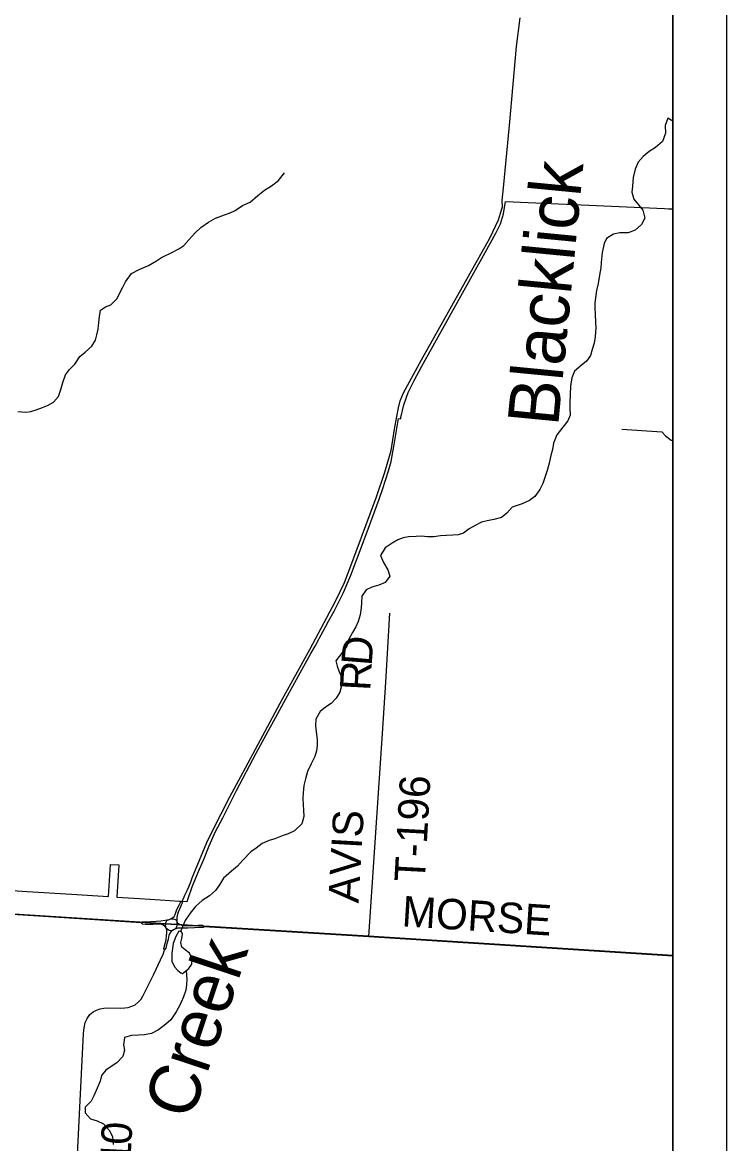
# Model space of a CAD drawing. Extents: x 208586767.6 to 208586821.4, y -134301046.9 to -134301022.9.
# Drawn here: x 208586783.617 to 208586784.928, y -134301027.656 to -134301025.568 of the extents above; entities that cross this region are included whole.
import ezdxf

# ---------------------------------------------------------------- set-up
doc = ezdxf.new("R2010")
doc.units = 0
for name, color, linetype in [('GM_X_Corporation', 7, 'Continuous'), ('GM_X_County_Road', 7, 'Continuous'), ('GM_X_County_Road_Text', 7, 'Continuous'), ('GM_X_Minor_Lake', 7, 'Continuous'), ('GM_X_Minor_River', 7, 'Continuous'), ('GM_X_Minor_River_Text', 7, 'Continuous'), ('GM_X_Township_Road', 7, 'Continuous'), ('GM_X_Township_Road_Text', 7, 'Continuous'), ('SH_Data', 7, 'Continuous')]:
    doc.layers.add(name, color=color, linetype=linetype)

msp = doc.modelspace()

# ---------------------------------------------------------------- linework, layer by layer
at = {"layer": 'GM_X_Corporation'}
for points in [[(208586781.2713, -134301027.0897), (208586781.6677, -134301027.1118), (208586781.7056, -134301027.1139), (208586781.7344, -134301027.1148), (208586781.8329, -134301027.1207), (208586781.8549, -134301027.122), (208586781.8736, -134301027.1231), (208586781.98, -134301027.1295), (208586782.1685, -134301027.1422), (208586782.6086, -134301027.1669), (208586782.6378, -134301027.1684), (208586782.648, -134301027.1691), (208586782.72, -134301027.1729), (208586782.8221, -134301027.178), (208586783.5221, -134301027.2233), (208586783.9036, -134301027.2474), (208586784.2616, -134301027.2694), (208586784.8283, -134301027.3051), (208586784.8283, -134301024.0407), (208586780.8686, -134301024.0407)], [(208586783.5332, -134301027.18), (208586783.6258, -134301027.1859), (208586783.7083, -134301027.1912), (208586783.7768, -134301027.1955), (208586783.7805, -134301027.1358), (208586783.7965, -134301027.1367), (208586783.7926, -134301027.1965), (208586783.8345, -134301027.1992), (208586783.873, -134301027.2016), (208586783.9093, -134301027.2039), (208586783.9118, -134301027.2041), (208586783.9236, -134301027.2048), (208586783.926, -134301027.1976), (208586783.933, -134301027.1775), (208586783.9397, -134301027.1609), (208586783.9466, -134301027.1445), (208586783.9538, -134301027.1281), (208586783.9645, -134301027.1012), (208586783.9765, -134301027.0747), (208586783.9898, -134301027.0489), (208586784.0157, -134301026.9984), (208586784.0524, -134301026.9285), (208586784.1076, -134301026.8271), (208586784.1537, -134301026.743), (208586784.1617, -134301026.7291), (208586784.1695, -134301026.7152), (208586784.1771, -134301026.7012), (208586784.1871, -134301026.6826), (208586784.1971, -134301026.6639), (208586784.207, -134301026.6453), (208586784.2146, -134301026.6294), (208586784.2217, -134301026.6133), (208586784.2285, -134301026.597), (208586784.2514, -134301026.5363), (208586784.2547, -134301026.5274), (208586784.257, -134301026.5212), (208586784.2814, -134301026.4555), (208586784.2876, -134301026.4378), (208586784.2931, -134301026.4204), (208586784.2983, -134301026.4029), (208586784.3038, -134301026.3854), (208586784.3094, -134301026.3536), (208586784.3174, -134301026.3054), (208586784.3214, -134301026.3056), (208586784.3217, -134301026.3036), (208586784.327, -134301026.2798), (208586784.3351, -134301026.2569), (208586784.3462, -134301026.2344), (208586784.3605, -134301026.208), (208586784.4786, -134301025.9959), (208586784.4987, -134301025.96), (208586784.5071, -134301025.9425), (208586784.5129, -134301025.9239), (208586784.5158, -134301025.9048), (208586784.5162, -134301025.9009), (208586784.8128, -134301025.9142), (208586784.82, -134301025.9145), (208586784.8283, -134301025.9149), (208586784.8283, -134301024.3829)], [(208586780.4561, -134301030.8407), (208586784.8283, -134301030.8407), (208586784.8283, -134301027.3051), (208586784.2616, -134301027.2694), (208586783.9036, -134301027.2474), (208586783.5221, -134301027.2233), (208586782.8221, -134301027.178), (208586782.72, -134301027.1729), (208586782.648, -134301027.1691), (208586782.6378, -134301027.1684), (208586782.6086, -134301027.1669), (208586782.1685, -134301027.1422), (208586781.98, -134301027.1295), (208586781.8736, -134301027.1231), (208586781.8549, -134301027.122), (208586781.8329, -134301027.1207), (208586781.7344, -134301027.1148), (208586781.7056, -134301027.1139), (208586781.6677, -134301027.1118), (208586781.2713, -134301027.0897)]]:
    msp.add_lwpolyline(points, dxfattribs=at)
at = {"layer": 'GM_X_County_Road'}
msp.add_line((208586783.5223, -134301027.2238), (208586783.837, -134301027.2437), dxfattribs=at)
for points in [[(208586783.9304, -134301027.168), (208586783.933, -134301027.1609), (208586783.9603, -134301027.0951), (208586783.9705, -134301027.0734), (208586784.0033, -134301027.0099), (208586784.0278, -134301026.964), (208586784.101, -134301026.8274), (208586784.1518, -134301026.7352), (208586784.2001, -134301026.6453), (208586784.2166, -134301026.6107), (208586784.2303, -134301026.5749), (208586784.2644, -134301026.4827), (208586784.2764, -134301026.4511), (208586784.2917, -134301026.4055), (208586784.2962, -134301026.3904), (208586784.3035, -134301026.365), (208586784.3095, -134301026.3251), (208586784.314, -134301026.3018), (208586784.317, -134301026.2853), (208586784.3202, -134301026.2723), (208586784.3268, -134301026.2575), (208586784.3598, -134301026.1959), (208586784.4475, -134301026.0399), (208586784.4872, -134301025.9696), (208586784.5034, -134301025.9351), (208586784.5071, -134301025.9231), (208586784.5109, -134301025.9111), (208586784.5102, -134301025.8995), (208586784.513, -134301025.8759), (208586784.5238, -134301025.7598), (208586784.531, -134301025.6828), (208586784.5371, -134301025.6123), (208586784.5436, -134301025.5592)], [(208586783.9147, -134301027.2034), (208586783.9195, -134301027.1928), (208586783.9241, -134301027.1832), (208586783.9267, -134301027.1772), (208586783.9304, -134301027.168)], [(208586783.8898, -134301027.2382), (208586783.8953, -134301027.2361), (208586783.8992, -134301027.233), (208586783.9012, -134301027.2289), (208586783.9046, -134301027.22), (208586783.909, -134301027.2103), (208586783.9115, -134301027.2053), (208586783.9147, -134301027.2034)], [(208586783.905, -134301027.2441), (208586783.9048, -134301027.2397), (208586783.905, -134301027.2342), (208586783.9062, -134301027.2284), (208586783.9074, -134301027.2238), (208586783.9099, -134301027.2183), (208586783.9132, -134301027.2111), (208586783.9149, -134301027.207), (208586783.9147, -134301027.2034)], [(208586783.837, -134301027.2437), (208586783.8398, -134301027.2429), (208586783.8477, -134301027.2425), (208586783.8558, -134301027.2422), (208586783.8658, -134301027.2416), (208586783.8746, -134301027.2406), (208586783.8829, -134301027.2394), (208586783.8898, -134301027.2382), (208586783.8916, -134301027.2376), (208586783.895, -134301027.2371), (208586783.8977, -134301027.2373), (208586783.9, -134301027.238), (208586783.9022, -134301027.2389), (208586783.9042, -134301027.2412), (208586783.905, -134301027.2441), (208586783.9078, -134301027.2465), (208586783.9136, -134301027.2492), (208586783.917, -134301027.2497), (208586783.9227, -134301027.2496), (208586783.9345, -134301027.2494), (208586783.9443, -134301027.2492), (208586783.9524, -134301027.2492), (208586783.9553, -134301027.2511)], [(208586783.837, -134301027.2437), (208586783.8398, -134301027.2464), (208586783.8459, -134301027.247), (208586783.8535, -134301027.2472), (208586783.8595, -134301027.2468), (208586783.8671, -134301027.2465), (208586783.8724, -134301027.2465), (208586783.8759, -134301027.2469), (208586783.8789, -134301027.2484), (208586783.8818, -134301027.251), (208586783.8841, -134301027.2536)], [(208586783.8841, -134301027.2536), (208586783.8836, -134301027.251), (208586783.883, -134301027.2485), (208586783.8833, -134301027.2455), (208586783.8842, -134301027.2429), (208586783.886, -134301027.2404), (208586783.8898, -134301027.2382)], [(208586783.9045, -134301027.2516), (208586783.9051, -134301027.2491), (208586783.905, -134301027.2441)], [(208586783.8812, -134301027.2956), (208586783.8801, -134301027.2923), (208586783.8826, -134301027.2833), (208586783.8843, -134301027.2763), (208586783.8853, -134301027.269), (208586783.8857, -134301027.2631), (208586783.8856, -134301027.2574), (208586783.8841, -134301027.2536)], [(208586783.8812, -134301027.2956), (208586783.8842, -134301027.292), (208586783.8866, -134301027.2832), (208586783.8888, -134301027.2747), (208586783.8898, -134301027.2677), (208586783.8911, -134301027.2643), (208586783.8941, -134301027.2605), (208586783.8964, -134301027.2585), (208586783.8996, -134301027.2566)], [(208586783.8841, -134301027.2536), (208586783.8864, -134301027.256), (208586783.8898, -134301027.258), (208586783.8935, -134301027.2587), (208586783.8963, -134301027.2582), (208586783.8996, -134301027.2566)], [(208586783.8996, -134301027.2566), (208586783.9029, -134301027.2552), (208586783.9074, -134301027.254), (208586783.9134, -134301027.2538), (208586783.9249, -134301027.2536), (208586783.9374, -134301027.2533), (208586783.9531, -134301027.2529), (208586783.9553, -134301027.2511)], [(208586783.8996, -134301027.2566), (208586783.9022, -134301027.2548), (208586783.9042, -134301027.2524), (208586783.9045, -134301027.2516)], [(208586783.9553, -134301027.2511), (208586784.2619, -134301027.27), (208586784.8283, -134301027.3057)], [(208586783.8742, -134301027.3132), (208586783.8787, -134301027.3027), (208586783.8805, -134301027.2971), (208586783.8812, -134301027.2956)], [(208586783.7156, -134301027.7514), (208586783.7306, -134301027.4507), (208586783.7315, -134301027.4398), (208586783.7337, -134301027.4303), (208586783.7372, -134301027.4225), (208586783.7421, -134301027.4155), (208586783.7485, -134301027.4101), (208586783.7547, -134301027.4069), (208586783.7617, -134301027.4045), (208586783.7683, -134301027.4032), (208586783.777, -134301027.4031), (208586783.8001, -134301027.4032), (208586783.8074, -134301027.4031), (208586783.8136, -134301027.402), (208586783.8204, -134301027.4), (208586783.8266, -134301027.3972), (208586783.8325, -134301027.3924), (208586783.8377, -134301027.3868), (208586783.8409, -134301027.3814), (208586783.8444, -134301027.375), (208586783.8613, -134301027.3402), (208586783.8742, -134301027.3132)]]:
    msp.add_lwpolyline(points, dxfattribs=at)
at = {"layer": 'GM_X_Minor_Lake'}
for points in [[(208586784.7331, -134301026.3252), (208586784.8078, -134301026.3302)], [(208586784.8078, -134301026.3302), (208586784.8146, -134301026.3375), (208586784.8252, -134301026.3459), (208586784.8283, -134301026.3467)], [(208586783.9264, -134301027.3293), (208586783.9321, -134301027.3217), (208586783.9326, -134301027.3115), (208586783.9281, -134301027.3008), (208586783.9201, -134301027.2951), (208586783.9137, -134301027.2897), (208586783.9119, -134301027.2814), (208586783.9134, -134301027.2738), (208586783.9146, -134301027.2654), (208586783.9131, -134301027.2613), (208586783.9078, -134301027.2601), (208586783.9025, -134301027.2699), (208586783.8978, -134301027.2828), (208586783.895, -134301027.301), (208586783.8953, -134301027.3158), (208586783.8998, -134301027.3265), (208586783.9062, -134301027.3333), (208586783.9119, -134301027.3379)], [(208586783.9119, -134301027.3379), (208586783.9142, -134301027.3389), (208586783.9148, -134301027.3389), (208586783.9264, -134301027.3293)]]:
    msp.add_lwpolyline(points, dxfattribs=at)
at = {"layer": 'GM_X_Minor_River'}
for points in [[(208586784.8283, -134301025.7514), (208586784.8187, -134301025.7462), (208586784.814, -134301025.7598), (208586784.8147, -134301025.7738), (208586784.8089, -134301025.7894), (208586784.7956, -134301025.8003), (208586784.7841, -134301025.8082), (208586784.7727, -134301025.8176), (208586784.7635, -134301025.8278), (208586784.7577, -134301025.8407), (208586784.7542, -134301025.8562), (208586784.753, -134301025.8725), (208586784.7518, -134301025.8835), (208586784.7555, -134301025.8965), (208586784.7642, -134301025.9071), (208586784.7725, -134301025.9174), (208586784.7758, -134301025.9323), (208586784.7696, -134301025.944), (208586784.7582, -134301025.9545), (208586784.7449, -134301025.9594), (208586784.7297, -134301025.9597), (208586784.7179, -134301025.9619), (208586784.7046, -134301025.9698), (208586784.7003, -134301025.9796), (208586784.6964, -134301025.9963), (208586784.6944, -134301026.0145), (208586784.694, -134301026.0244), (208586784.6916, -134301026.0384), (208586784.6892, -134301026.0536), (208586784.6861, -134301026.0668), (208586784.6845, -134301026.0763), (208586784.6829, -134301026.09), (208586784.6829, -134301026.0998), (208586784.6832, -134301026.1101), (208586784.6839, -134301026.1272), (208586784.6845, -134301026.1367), (208586784.6837, -134301026.1526), (208586784.6817, -134301026.1647), (208586784.6782, -134301026.1769), (208586784.6747, -134301026.1882), (208586784.6671, -134301026.1984), (208586784.6575, -134301026.2067), (208586784.645, -134301026.2169), (208586784.6399, -134301026.2294), (208586784.6376, -134301026.2453), (208586784.6367, -134301026.2605), (208586784.6362, -134301026.2761), (208586784.6366, -134301026.2859), (208586784.6369, -134301026.2988), (208586784.6326, -134301026.3098), (208586784.6234, -134301026.3215), (208586784.6123, -134301026.3359), (208586784.6062, -134301026.351), (208586784.6038, -134301026.3632), (208586784.6011, -134301026.3742), (208586784.598, -134301026.3882), (208586784.5941, -134301026.4022), (208586784.5898, -134301026.4151), (208586784.5863, -134301026.4265), (208586784.5806, -134301026.4378), (208586784.5714, -134301026.4507), (208586784.5611, -134301026.4582), (208586784.5478, -134301026.4642), (208586784.5383, -134301026.4675), (208586784.5288, -134301026.4705), (208586784.5188, -134301026.4815), (208586784.5089, -134301026.4898), (208586784.4945, -134301026.4935), (208586784.4823, -134301026.4957), (208586784.472, -134301026.4986), (208586784.4598, -134301026.5043), (208586784.4488, -134301026.5107), (208586784.4385, -134301026.5189), (208586784.4286, -134301026.5219), (208586784.4184, -134301026.5226), (208586784.4066, -134301026.5233), (208586784.3956, -134301026.524), (208586784.383, -134301026.5254), (208586784.3713, -134301026.5254), (208586784.3599, -134301026.5245), (208586784.35, -134301026.5249), (208586784.3356, -134301026.5255), (208586784.3257, -134301026.5278), (208586784.3158, -134301026.5311), (208586784.3056, -134301026.5375), (208586784.2926, -134301026.5462), (208586784.2838, -134301026.5602), (208586784.2894, -134301026.5735), (208586784.2973, -134301026.5872), (208586784.301, -134301026.599), (208586784.2926, -134301026.6107), (208586784.2808, -134301026.6156), (208586784.2678, -134301026.6193), (208586784.2572, -134301026.6245), (208586784.2488, -134301026.6359)], [(208586783.6084, -134301026.2923), (208586783.6232, -134301026.2932), (208586783.6327, -134301026.2921), (208586783.6426, -134301026.2891), (208586783.654, -134301026.285), (208586783.6635, -134301026.2813), (208586783.6745, -134301026.2749), (208586783.6837, -134301026.2643), (208586783.6883, -134301026.2514), (208586783.6922, -134301026.2382), (208586783.6969, -134301026.2242), (208586783.7045, -134301026.2143), (208586783.7144, -134301026.2041), (208586783.7236, -134301026.1898), (208586783.7336, -134301026.1815), (208586783.7458, -134301026.1705), (208586783.7527, -134301026.1592), (208586783.7554, -134301026.1497), (208586783.7577, -134301026.1387), (208586783.7593, -134301026.1262), (208586783.7602, -134301026.1156), (208586783.7621, -134301026.1038), (208586783.7717, -134301026.0974), (208586783.7812, -134301026.0937), (208586783.7934, -134301026.082), (208586783.7984, -134301026.071), (208586783.8038, -134301026.0608), (208586783.8088, -134301026.051), (208586783.8199, -134301026.0355), (208586783.8343, -134301026.0276), (208586783.8518, -134301026.0201), (208586783.8663, -134301026.0119), (208586783.8759, -134301026.0055), (208586783.896, -134301025.9957), (208586783.9078, -134301025.9893), (208586783.9174, -134301025.9829), (208586783.9269, -134301025.9727), (208586783.9376, -134301025.9603), (208586783.9491, -134301025.9497), (208586783.9636, -134301025.9399), (208586783.9761, -134301025.9321), (208586783.9932, -134301025.9261), (208586784.0035, -134301025.922), (208586784.013, -134301025.9178), (208586784.0264, -134301025.9084), (208586784.0408, -134301025.9025), (208586784.0553, -134301025.89), (208586784.0675, -134301025.8802), (208586784.0809, -134301025.8719), (208586784.0938, -134301025.8622), (208586784.1049, -134301025.8478)], [(208586784.2488, -134301026.6359), (208586784.2483, -134301026.6484), (208586784.2479, -134301026.6582), (208586784.2455, -134301026.6708), (208586784.242, -134301026.6833), (208586784.2378, -134301026.6931), (208586784.2313, -134301026.7037), (208586784.2243, -134301026.7173), (208586784.2209, -134301026.7291), (208586784.2132, -134301026.7404), (208586784.2006, -134301026.7567), (208586784.2032, -134301026.7665), (208586784.2069, -134301026.7772), (208586784.2114, -134301026.7878), (208586784.2121, -134301026.7985), (208586784.2082, -134301026.8148), (208586784.2013, -134301026.8261), (208586784.1921, -134301026.8363), (208586784.1814, -134301026.8431), (208586784.1715, -134301026.851), (208586784.1631, -134301026.865), (208586784.1626, -134301026.8779), (208586784.1637, -134301026.8889), (208586784.1659, -134301026.9033), (208586784.1658, -134301026.9136), (208586784.1646, -134301026.9242), (208586784.1611, -134301026.9348), (208586784.1546, -134301026.9484), (208586784.148, -134301026.9624), (208586784.1438, -134301026.9765), (208586784.141, -134301026.989), (208586784.1394, -134301027.0022), (208586784.139, -134301027.0121), (208586784.1397, -134301027.025), (208586784.1404, -134301027.0349), (208586784.1407, -134301027.0467), (208586784.1372, -134301027.0603), (208586784.1234, -134301027.0735), (208586784.1116, -134301027.0791), (208586784.1021, -134301027.0821), (208586784.0869, -134301027.0881), (208586784.0763, -134301027.0914), (208586784.0633, -134301027.0967), (208586784.0519, -134301027.1053), (208586784.042, -134301027.1125), (208586784.0271, -134301027.1276), (208586784.0171, -134301027.1389), (208586784.0064, -134301027.1483), (208586783.9912, -134301027.1611), (208586783.9835, -134301027.174), (208586783.9766, -134301027.1842), (208586783.9652, -134301027.1944), (208586783.9518, -134301027.203), (208586783.9392, -134301027.214), (208586783.9289, -134301027.2264), (208586783.9197, -134301027.2404), (208586783.9109, -134301027.2608)], [(208586783.9216, -134301027.3332), (208586783.9228, -134301027.3494), (208586783.9224, -134301027.3592), (208586783.9212, -134301027.3702), (208586783.9169, -134301027.3824), (208586783.9104, -134301027.3964), (208586783.9031, -134301027.41), (208586783.8931, -134301027.4255), (208586783.8836, -134301027.4334), (208586783.8699, -134301027.4439), (208586783.8569, -134301027.4507), (208586783.844, -134301027.4529), (208586783.833, -134301027.4536), (208586783.8201, -134301027.4546), (208586783.8071, -134301027.458), (208586783.8048, -134301027.4716), (208586783.807, -134301027.4819), (208586783.8035, -134301027.4936), (208586783.7924, -134301027.505), (208586783.7818, -134301027.5121), (208586783.7722, -134301027.5189), (208586783.7638, -134301027.5291), (208586783.7615, -134301027.5393), (208586783.7561, -134301027.5522), (208586783.7495, -134301027.5666), (208586783.7449, -134301027.5764), (208586783.7338, -134301027.5881), (208586783.7338, -134301027.5983), (208586783.7436, -134301027.6094), (208586783.7561, -134301027.6133), (208586783.7678, -134301027.619), (208586783.7784, -134301027.6309), (208586783.7844, -134301027.6427), (208586783.7858, -134301027.6575)]]:
    msp.add_lwpolyline(points, dxfattribs=at)
at = {"layer": 'GM_X_Township_Road'}
msp.add_line((208586784.2935, -134301026.7961), (208586784.3012, -134301026.6678), dxfattribs=at)
msp.add_lwpolyline([(208586784.2619, -134301027.27), (208586784.2877, -134301026.8917), (208586784.2935, -134301026.7961)], dxfattribs=at)
at = {"layer": 'SH_Data'}
for p, q in [((208586784.9283, -134301023.9407), (208586784.9283, -134301030.9407)), ((208586784.8283, -134301024.0407), (208586784.8283, -134301030.8407))]:
    msp.add_line(p, q, dxfattribs=at)

# ---------------------------------------------------------------- texts
at = {"layer": 'GM_X_County_Road_Text'}
for s, height, rotation, p in [('MORSE', 0.05682, 356.3984, (208586784.3224, -134301027.2509)), ('0', 0.0568, 87.0871, (208586783.8196, -134301027.6589)), ('1', 0.0568, 87.0466, (208586783.8178, -134301027.6939))]:
    msp.add_text(s, height=height, rotation=rotation, dxfattribs=at).set_placement(p)
at = {"layer": 'GM_X_Minor_River_Text'}
for s, height, rotation, p in [('Blacklick', 0.09471, 84.4805, (208586784.6144, -134301026.3211)), ('Creek', 0.0947, 71.5253, (208586783.9312, -134301027.6147))]:
    msp.add_text(s, height=height, rotation=rotation, dxfattribs=at).set_placement(p)
at = {"layer": 'GM_X_Township_Road_Text'}
for s, height, rotation, p in [('D', 0.0568, 85.4197, (208586784.267, -134301026.767)), ('R', 0.0568, 86.8877, (208586784.2645, -134301026.8132)), ('T-196', 0.05682, 86.9141, (208586784.3662, -134301027.1694)), ('AVIS', 0.05682, 86.7543, (208586784.2429, -134301027.2087))]:
    msp.add_text(s, height=height, rotation=rotation, dxfattribs=at).set_placement(p)

doc.saveas('drawing.dxf')
